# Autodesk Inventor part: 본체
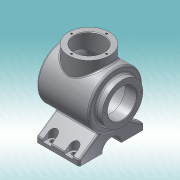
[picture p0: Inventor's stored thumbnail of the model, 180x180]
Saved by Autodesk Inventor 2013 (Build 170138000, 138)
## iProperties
Created: 2017-04
Part Number: 본체
Material: 알루미늄 6061
Document SubType Name: Modeling
Designer: dgall
Density: 2.71 g/cm^3
Mass: 1670.63 g
Surface Area: 1067.16 cm^2
Volume: 616.468 cm^3
Author: dgall
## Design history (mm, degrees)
sketch "스케치1"
  geometry: L1 (0, 0)-(120, 0); L2 (0, 0)-(0, 27); L3 (0, 27)-(22, 27); L4 (0, 27)-(0, 38); L5 (0, 38)-(9, 38); L6 (12, 41)-(12, 47); L7 (7, 0)-(120, 0); L8 (15, 50)-(106.454, 50); L9 (25, 40)-(99.903, 40); L10 (22, 27)-(22, 37); L11 (110, 0)-(120, 0); A1 r 113 centre (7, 0) between (120, 0) and (109.166, 48.282); A2 r 103 centre (7, 0) between (110, 0) and (102.69, 38.11); A3 r 3 centre (9, 41) between (9, 38) and (12, 41); A4 r 3 centre (15, 47) between (15, 50) and (12, 47); A5 r 3 centre (106.454, 47) between (109.166, 48.282) and (106.454, 50); A6 r 3 centre (99.903, 37) between (102.69, 38.11) and (99.903, 40); A7 r 3 centre (25, 37) between (25, 40) and (22, 37); 4 further points
  constraints: 22 end point, 16 point on circle, 10 tangent, 7 centre point, 7 perpendicular, 7 point on line, 4 equal radius, 2 coincident, 1 collinear, 1 horizontal, 1 horizontal alignment, 1 parallel
  dimensions: "d0" = 120 distance of L1.start L1.end; "d1" = 27 distance of L1.start L2.end; "d2" = 22 distance of L2.end L3.end; "d3" = 11 distance of L2.end L4.end; "d4" = 12 distance of L4.end point (12, 38); "d5" = 12 distance of point (12, 38) point (12, 50); "d8" = 113 radius of A1; "d9" = 5 distance from line of L7.start L6; "d10" = 10 radial gap between concentric circles of A1 A2; "d11" = 10 distance between parallel lines of L8 L9; "d12" = 3 radius of A3
revolve "회전1" sketch "스케치1" stored, may be unused: angle "d13" = 90 deg
node "작업 평면1"
sketch "스케치2"
  geometry: L1 (-12, 47)-(-12, -47) reference; C1 r 38 at (-62, 0); C2 r 27 at (-62, 0); 1 further point
  constraints: 2 centre point, 1 coincident, 1 horizontal alignment
  dimensions: "d15" = 38 radius of C1; "d17" = 50 distance from line of C1.centre L1; "d18" = 27 radius of C2
extrude "돌출1" join sketch "스케치2" stored distance "d19" = 10; taper "d20" = 0 deg
extrude "돌출2" cut sketch "스케치2" stored distance "d21" = 10; taper "d22" = 0 deg
node "작업 평면2"
sketch "스케치3"
  geometry: L1 (-60, -82)-(60, -82); L2 (60, -82)-(60, -72); L3 (60, -72)-(21.584, -45.101); L4 (-60, -82)-(-60, -72); L5 (-60, -72)-(-21.584, -45.101); A1 r 50 centre (0, 0) between (21.584, -45.101) and (-21.584, -45.101) reference; A2 r 18 centre (0, -82) between (18, -82) and (-18, -82); 2 further points
  constraints: 10 end point, 4 point on circle, 2 point on line, 1 centre point, 1 coincident, 1 equal length, 1 horizontal, 1 midpoint, 1 parallel, 1 perpendicular, 1 vertical alignment
  dimensions: "d24" = 120 distance of L1.start L1.end; "d25" = 82 distance from line of L1 point (0, 0); "d26" = 18 radius of A2; "d27" = 10 distance of L1.end L2.end; "d28" = 10 distance of L1.start L4.end; "d29" = 55 deg angle of L2 L3
extrude "돌출3" join sketch "스케치3" stored distance "d30" = 80; taper "d31" = 0 deg
node "작업 평면3"
sketch "스케치4"
  geometry: L1 (0, -42)-(0, 0) reference; L2 (80, 0)-(0, 0) reference; L3 (0, -42)-(0, 0) reference; L4 (0, -42)-(80, -42) reference; L5 (80, 0)-(80, -42) reference; L6 (28, -32)-(28, -42); L7 (12, -32)-(12, -42); L8 (28, -42)-(16, -42); C1 r 4 at (20, -32); A1 r 8 centre (20, -32) between (28, -32) and (12, -32); 1 further point
  constraints: 6 end point, 3 point on line, 2 centre point, 2 perpendicular, 2 point on circle, 2 tangent, 1 coincident
  dimensions: "d33" = 8 radius of A1; "d34" = 20 distance from line of L1 A1.centre; "d35" = 10 distance from line of L4 A1.centre; "d36" = 4 radius of C1
  node "투영된 루프1"
extrude "돌출4" cut sketch "스케치4" stored distance "d37" = 80; taper "d38" = 0 deg
extrude "돌출5" cut sketch "스케치4" stored distance "d39" = 80; taper "d40" = 0 deg
node "작업 평면4"
sketch "스케치5" dims "d42" = 32.5
  geometry: C1 r 38 at (0, 0) reference; C2 r 27 at (0, 0) reference; 2 further points
  constraints: 2 vertical alignment, 1 coincident, 2 other
hole "구멍1" sketch "스케치5" at (0, 32.5) diameter "d44" = 3.242; stored, may be unused: countersink angle "d48" = 90 deg, drill point angle "d50" = 118 deg; dims "d45" = 8, "d46" = 4, "d47" = 2, "d49" = 10
sketch "스케치6" dims "d54" = 32.5
  geometry: C1 r 27 at (0, 0) reference; C2 r 38 at (0, 0) reference; 3 further points
  constraints: 2 vertical alignment, 1 coincident, 2 other
hole "구멍2" sketch "스케치6" at (0, 32.5) diameter "d56" = 3.459; stored, may be unused: countersink angle "d60" = 90 deg, drill point angle "d62" = 118 deg; dims "d57" = 8, "d58" = 4, "d59" = 2, "d61" = 10
fillet "모깎기1" dims "d66" = 3
fillet "모깎기2" dims "d67" = 3
fillet "모깎기3" dims "d68" = 3
node "작업 평면6"
sketch "스케치7"
  geometry: 2 further points
  constraints: 2 coincident, 1 other
feature "엠보싱1" sketch "스케치7" dims "d0" = 120, "d1" = 27, "d2" = 22, "d3" = 11, "d4" = 12, "d5" = 12, "d8" = 113, "d9" = 5, "d10" = 10, "d11" = 10, "d12" = 3, "d71" = 0.5, "d72" = 0
chamfer "모따기1" distance "d73" = 1; stored, may be unused: second distance "d74" = 2, angle "d75" = 45 deg
node "솔리드1"
mirror "대칭1"
mirror "대칭2"
pattern_circular "원형 패턴1" dims angle "d52" = 360 deg
pattern_circular "원형 패턴2" dims angle "d64" = 360 deg
other parameters: "d14" = 65, "d32" = -6, "d70" = 20.5
